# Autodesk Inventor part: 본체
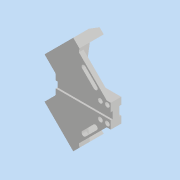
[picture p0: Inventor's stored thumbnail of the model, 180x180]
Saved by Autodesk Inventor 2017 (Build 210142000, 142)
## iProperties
Part Number: 본체
Material: 일반
Document SubType Name: Modeling
Designer: mrc
Density: 1 g/cm^3
Appearance: 기본값
Mass: 211.712 g
Surface Area: 407.173 cm^2
Volume: 211.712 cm^3
Author: mrc
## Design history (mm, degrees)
sketch "스케치3"
  geometry: L1 (84.853, 0)-(0, 84.853); L2 (0, 84.853)-(-84.853, 0); L3 (-84.853, 0)-(0, -84.853); L4 (0, -84.853)-(84.853, 0); 1 further point
  constraints: 8 end point, 2 horizontal alignment, 2 parallel, 1 perpendicular, 1 vertical alignment
  dimensions: "d10" = 120 distance of L2.end L3.end; "d11" = 120 distance of L1.end L2.end
extrude "돌출2" new body sketch "스케치3" distance "d12" = 18; taper "d13" = 0 deg
sketch "스케치5"
  geometry: L1 (-49.497, 35.355)-(-30.147, 16.005); L2 (-30.147, -16.005)-(-49.497, -35.355); L3 (0, 84.853)-(-84.853, 0) reference; L4 (-84.853, 0)-(0, -84.853) reference; L5 (-49.497, -35.355)-(-84.853, 0); L6 (-84.853, 0)-(-49.497, 35.355); L7 (64.853, -20)-(64.853, 20); L8 (84.853, 0)-(0, 84.853) reference; L9 (0, -84.853)-(84.853, 0) reference; L10 (-30.147, -16.005)-(-30.147, 16.005); L11 (64.853, -20)-(84.853, 0); L12 (64.853, 20)-(84.853, 0); 1 further point
  constraints: 16 end point, 4 collinear, 3 point on line, 2 parallel, 2 vertical
  dimensions: "d14" = 50 distance between parallel lines of L3 L2; "d15" = 50 distance between parallel lines of L1 L4; "d16" = 40 distance of L7.start L7.end; "d18" = 95 distance between parallel lines of L7 L10
extrude "돌출3" cut sketch "스케치5" stored distance "d19" = 18; taper "d20" = 0 deg
sketch "스케치6"
  geometry: L1 (-38.891, -24.749)-(10.607, -74.246); L2 (-49.497, -35.355)-(0, -84.853) reference; L3 (-38.891, 24.749)-(10.607, 74.246); L4 (0, 84.853)-(-49.497, 35.355) reference; L5 (-49.497, 35.355)-(-30.147, 16.005) reference; L6 (-30.147, -16.005)-(-49.497, -35.355) reference; L7 (64.853, 20)-(0, 84.853) reference; L8 (0, -84.853)-(64.853, -20) reference; L9 (10.607, -74.246)-(0, -84.853); L10 (-49.497, -35.355)-(0, -84.853); L11 (-49.497, -35.355)-(-38.891, -24.749); L12 (-38.891, 24.749)-(-49.497, 35.355); L13 (-49.497, 35.355)-(0, 84.853); L14 (0, 84.853)-(10.607, 74.246); L15 (64.853, 20)-(0, 84.853) reference; 1 further point
  constraints: 16 end point, 4 collinear, 2 parallel, 2 point on line
  dimensions: "d21" = 15 distance between parallel lines of L1 L2; "d22" = 15 distance between parallel lines of L3 L4
extrude "돌출4" join sketch "스케치6" distance "d23" = 24; taper "d24" = 0 deg
sketch "스케치7"
  geometry: L1 (10.607, -74.246)-(64.853, -20) reference; L2 (64.853, 20)-(10.607, 74.246) reference; L3 (7.071, -70.711)-(57.782, -20); L4 (57.782, 20)-(7.071, 70.711); L5 (-49.497, -35.355)-(0, -84.853) reference; L6 (0, 84.853)-(-49.497, 35.355) reference; L7 (10.607, -74.246)-(-38.891, -24.749) reference; L8 (-38.891, 24.749)-(10.607, 74.246) reference; L9 (64.853, 20)-(64.853, -20) reference; L10 (0, -84.853)-(64.853, -20) reference; L11 (64.853, -20)-(57.782, -20); L12 (64.853, 20)-(0, 84.853) reference; L13 (64.853, 20)-(57.782, 20); L14 (7.071, 70.711)-(10.607, 74.246); L15 (10.607, 74.246)-(64.853, 20); L16 (64.853, -20)-(10.607, -74.246); L17 (10.607, -74.246)-(7.071, -70.711); 1 further point
  constraints: 16 end point, 3 collinear, 2 horizontal, 2 parallel, 1 perpendicular
  dimensions: "d25" = 5 distance between parallel lines of L1 L3; "d26" = 5 distance between parallel lines of L2 L4
extrude "돌출5" cut sketch "스케치7" stored distance "d31" = 24; taper "d32" = 0 deg
sketch "스케치8"
  geometry: L1 (7.071, -70.711)-(57.782, -20) reference; L2 (57.782, -20)-(64.853, -20) reference; L3 (64.853, -20)-(64.853, 20) reference; L4 (64.853, 20)-(57.782, 20) reference; L5 (57.782, 20)-(7.071, 70.711) reference; L6 (7.071, 70.711)-(-38.891, 24.749) reference; L7 (-38.891, 24.749)-(-30.147, 16.005) reference; L8 (-30.147, 16.005)-(-30.147, -16.005) reference; L9 (-30.147, -16.005)-(-38.891, -24.749) reference; L10 (-38.891, -24.749)-(7.071, -70.711) reference; L11 (-38.891, -24.749)-(-49.497, -35.355) reference; L12 (-49.497, -35.355)-(0, -84.853) reference; L13 (0, -84.853)-(10.607, -74.246) reference; L14 (10.607, -74.246)-(-38.891, -24.749) reference; L15 (-38.891, 24.749)-(10.607, 74.246) reference; L16 (10.607, 74.246)-(0, 84.853) reference; L17 (0, 84.853)-(-49.497, 35.355) reference; L18 (-49.497, 35.355)-(-38.891, 24.749) reference; L19 (57.782, -20)-(7.071, -70.711) reference; L20 (57.782, -20)-(36.569, -20); L21 (7.071, -70.711)-(7.071, -49.497); L22 (7.071, -49.497)-(36.569, -20); L23 (7.071, 49.497)-(7.071, 70.711); L24 (57.782, 20)-(36.569, 20); L25 (36.569, 20)-(7.071, 49.497); 1 further point
  constraints: 12 end point, 2 horizontal, 2 parallel
  dimensions: "d35" = 20 distance between parallel lines of L13 L22; "d36" = 30 distance from line of L21.end L12; "d39" = 20 distance between parallel lines of L16 L25; "d40" = 30 distance from line of L23.start L17
extrude "돌출6" cut sketch "스케치8" distance "d41" = 10; taper "d42" = 0 deg
sketch "스케치9"
  geometry: L1 (18.385, -49.497)-(38.184, -29.698); L2 (21.213, -52.326)-(41.012, -32.527); L3 (35.355, -26.87)-(15.556, -46.669); L4 (57.782, -20)-(7.071, -70.711) reference; L5 (-49.497, -35.355)-(0, -84.853) reference; L6 (0, -84.853)-(10.607, -74.246) reference; A1 r 4 centre (18.385, -49.497) between (15.556, -46.669) and (21.213, -52.326); A2 r 4 centre (38.184, -29.698) between (41.012, -32.527) and (35.355, -26.87); 2 further points
  constraints: 8 end point, 4 point on circle, 4 tangent, 2 centre point, 2 parallel, 1 midpoint
  dimensions: "d43" = 38 distance from line of L1.start L5; "d44" = 28 distance of L1.end L1.start; "d45" = 8 distance between parallel lines of L2 L3; "d46" = 12 distance from line of point (28.284, -39.598) L6
extrude "돌출7" cut sketch "스케치9" distance "d47" = 10; taper "d48" = 0 deg
sketch "스케치10"
  geometry: L1 (64.853, 20)-(64.853, -20) reference; C1 r 2.25 at (46.853, -14); 1 further point
  constraints: 1 centre point
  dimensions: "d51" = 4.5 diameter of C1; "d52" = 18 distance from line of L1 C1.centre; "d53" = 14 vertical distance of point (0, 0) C1.centre
extrude "돌출8" cut sketch "스케치10" distance "d54" = 8; taper "d55" = 0 deg
sketch "스케치11"
  geometry: C1 r 4 at (0, 0); C2 r 2.25 at (0, 0) reference; 1 further point
  constraints: 1 centre point, 1 concentric
  dimensions: "d56" = 8 diameter of C1
extrude "돌출9" cut sketch "스케치11" distance "d57" = 10; taper "d58" = 0 deg
sketch "스케치12"
  geometry: L1 (-30.147, -8)-(64.853, -8); L2 (64.853, -8)-(64.853, 8); L3 (64.853, 8)-(-30.147, 8); L4 (-30.147, 8)-(-30.147, -8); L5 (-30.147, -8)-(64.853, 8); L6 (64.853, -8)-(-30.147, 8); L7 (-30.147, 16.005)-(-30.147, -16.005) reference; 3 further points
  constraints: 12 end point, 3 midpoint, 2 parallel, 1 horizontal, 1 horizontal alignment, 1 perpendicular, 1 point on line
  dimensions: "d66" = 16 distance of L2.end L1.end; "d67" = 95 distance between parallel lines of L2 L4
extrude "돌출10" cut sketch "스케치12" distance "d68" = 3.5; taper "d69" = 0 deg
sketch "스케치13"
  geometry: L1 (64.853, -6)-(-30.147, -6); L2 (-30.147, -6)-(-30.147, 6); L3 (-30.147, 6)-(64.853, 6); L4 (64.853, 6)-(64.853, -6); L5 (64.853, -6)-(-30.147, 6); L6 (-30.147, -6)-(64.853, 6); L7 (64.853, -20)-(64.853, 20) reference; 3 further points
  constraints: 12 end point, 3 midpoint, 2 parallel, 1 horizontal, 1 horizontal alignment, 1 perpendicular, 1 point on line
  dimensions: "d70" = 12 distance of L1.end L2.end; "d71" = 95 distance of L1.start L1.end
extrude "돌출11" cut sketch "스케치13" distance "d72" = 3; taper "d73" = 0 deg
chamfer "모따기1" distance "d74" = 5; stored, may be unused: second distance "d75" = 15, angle "d76" = 45 deg
chamfer "모따기2" distance "d77" = 5; stored, may be unused: second distance "d78" = 15, angle "d79" = 45 deg
fillet "모깎기2" dims "d81" = 5
sketch "스케치15"
  geometry: L1 (10.607, -74.246)-(-38.891, -24.749) reference; L2 (-38.891, -24.749)-(-45.962, -31.82) reference; 2 further points
  constraints: 1 other
  dimensions: "d82" = 5 distance from line of L1 point (-17.678, -53.033); "d83" = 35 distance from line of L2 point (-17.678, -53.033)
feature "엠보싱1" sketch "스케치15" dims "d10" = 120, "d11" = 120, "d19" = 18, "d20" = 0, "d84" = 0.5, "d85" = 0
sketch "스케치16"
  geometry: L1 (7.071, -49.497)-(10.607, -74.246); L2 (7.071, -70.711)-(10.607, -74.246) reference; L3 (10.607, -74.246)-(7.071, -70.711); L4 (7.071, -70.711)-(7.071, -49.497) reference; L5 (7.071, -70.711)-(7.071, -49.497); 1 further point
  constraints: 6 end point, 2 collinear
extrude "돌출12" join sketch "스케치16" distance "d86" = 18; taper "d87" = 0 deg
fillet "모깎기3" dims "d88" = 5
node "솔리드2"
pattern_linear "직사각형 패턴1" dims "d61" = 12, "d64" = 28
mirror "미러1"
mirror "미러2"
node "투영된 루프1"
node "투영된 루프2"
node "투영된 루프3"
other parameters: "d17" = 95
